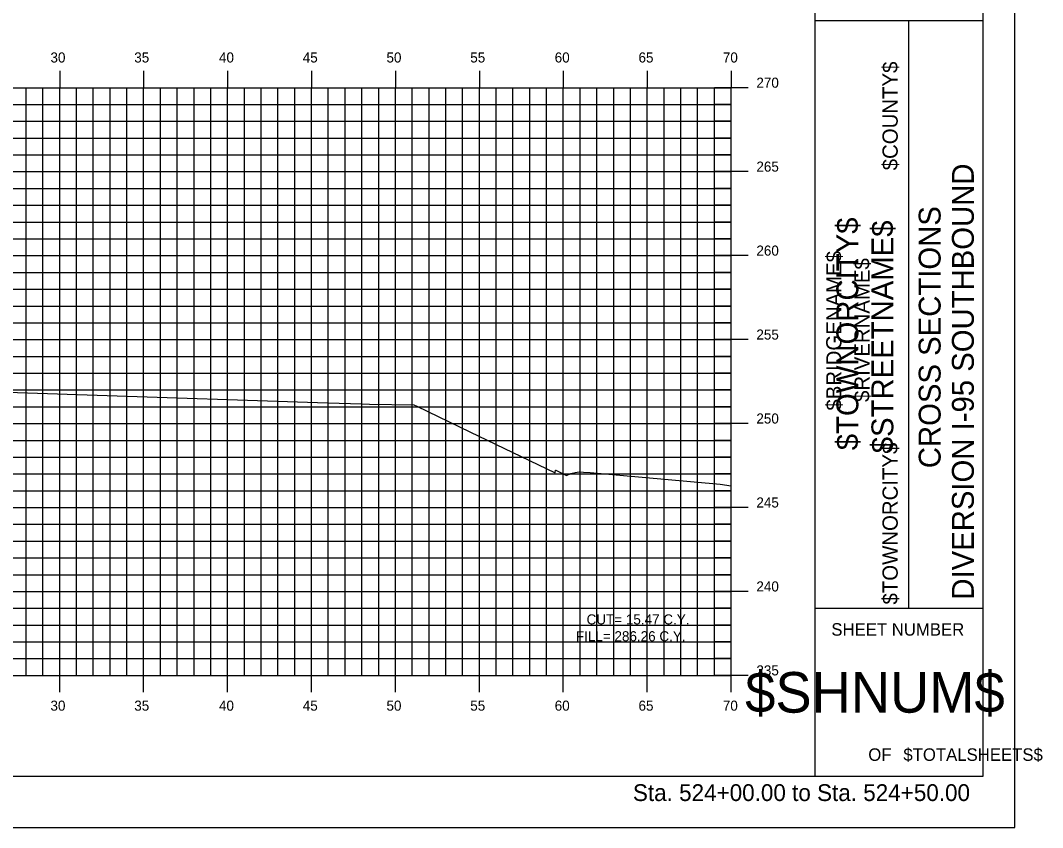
# Model space of a CAD drawing. Extents: x 1170543 to 1177585, y 609599 to 610623.
# Drawn here: x 1175384.7 to 1175445.6, y 609598.8 to 609646.9 of the extents above; entities that cross this region are included whole.
import ezdxf

# ---------------------------------------------------------------- set-up
doc = ezdxf.new("R2010")
doc.units = 0
for name, color, linetype in [('BORDER', 7, 'Continuous'), ('BRIDGE_TITLE', 7, 'Continuous'), ('D_Roadway_Centerline_Text', 7, 'Continuous'), ('H_V ANNOTATION', 7, 'Continuous'), ('HIGHWAY_TITLE', 7, 'Continuous'), ('MAJOR', 7, 'Continuous'), ('MINOR', 7, 'Continuous'), ('PLOT BOUNDARY', 7, 'Continuous'), ('S_Roadway_Centerline', 7, 'Continuous')]:
    doc.layers.add(name, color=color, linetype=linetype)

msp = doc.modelspace()

# ---------------------------------------------------------------- linework, layer by layer
at = {"layer": 'BORDER'}
for p, q in [((1175432.07, 609601.875), (1175432.07, 609706.875)), ((1175442.07, 609601.875), (1175442.07, 609706.875)), ((1175432.07, 609646.875), (1175442.07, 609646.875)), ((1175437.661, 609611.875), (1175437.661, 609646.875)), ((1175432.07, 609611.875), (1175442.07, 609611.875)), ((1175282.07, 609601.872), (1175442.07, 609601.872))]:
    msp.add_line(p, q, dxfattribs=at)
at = {"layer": 'MAJOR'}
for p, q in [((1175387.07, 609643.874), (1175387.07, 609642.872)), ((1175392.07, 609643.874), (1175392.07, 609642.872)), ((1175397.07, 609643.874), (1175397.07, 609642.872)), ((1175402.07, 609643.874), (1175402.07, 609642.872)), ((1175407.07, 609643.874), (1175407.07, 609642.872)), ((1175412.07, 609643.874), (1175412.07, 609642.872)), ((1175417.07, 609643.874), (1175417.07, 609642.872)), ((1175422.07, 609643.874), (1175422.07, 609642.872)), ((1175427.07, 609643.874), (1175427.07, 609642.872)), ((1175287.07, 609642.872), (1175427.07, 609642.872)), ((1175287.07, 609642.872), (1175427.07, 609642.872)), ((1175387.07, 609607.872), (1175387.07, 609642.872)), ((1175392.07, 609607.872), (1175392.07, 609642.872)), ((1175397.07, 609607.872), (1175397.07, 609642.872)), ((1175402.07, 609607.872), (1175402.07, 609642.872)), ((1175407.07, 609607.872), (1175407.07, 609642.872)), ((1175412.07, 609607.872), (1175412.07, 609642.872)), ((1175417.07, 609607.872), (1175417.07, 609642.872)), ((1175422.07, 609607.872), (1175422.07, 609642.872)), ((1175428.072, 609642.872), (1175426.068, 609642.872)), ((1175427.07, 609607.872), (1175427.07, 609642.872)), ((1175427.07, 609607.872), (1175427.07, 609642.872)), ((1175287.07, 609637.872), (1175427.07, 609637.872)), ((1175428.072, 609637.872), (1175426.068, 609637.872)), ((1175287.07, 609632.872), (1175427.07, 609632.872)), ((1175428.072, 609632.872), (1175426.068, 609632.872)), ((1175287.07, 609627.872), (1175427.07, 609627.872)), ((1175428.072, 609627.872), (1175426.068, 609627.872)), ((1175287.07, 609622.872), (1175427.07, 609622.872)), ((1175428.072, 609622.872), (1175426.068, 609622.872)), ((1175287.07, 609617.872), (1175427.07, 609617.872)), ((1175428.072, 609617.872), (1175426.068, 609617.872)), ((1175287.07, 609612.872), (1175427.07, 609612.872)), ((1175428.072, 609612.872), (1175426.068, 609612.872)), ((1175287.07, 609607.872), (1175427.07, 609607.872)), ((1175287.07, 609607.872), (1175427.07, 609607.872)), ((1175387.07, 609606.87), (1175387.07, 609607.872)), ((1175392.07, 609606.87), (1175392.07, 609607.872)), ((1175397.07, 609606.87), (1175397.07, 609607.872)), ((1175402.07, 609606.87), (1175402.07, 609607.872)), ((1175407.07, 609606.87), (1175407.07, 609607.872)), ((1175412.07, 609606.87), (1175412.07, 609607.872)), ((1175417.07, 609606.87), (1175417.07, 609607.872)), ((1175422.07, 609606.87), (1175422.07, 609607.872)), ((1175428.072, 609607.872), (1175426.068, 609607.872)), ((1175427.07, 609606.87), (1175427.07, 609607.872))]:
    msp.add_line(p, q, dxfattribs=at)
at = {"layer": 'MINOR'}
for p, q in [((1175385.07, 609607.872), (1175385.07, 609642.872)), ((1175386.07, 609607.872), (1175386.07, 609642.872)), ((1175388.07, 609607.872), (1175388.07, 609642.872)), ((1175389.07, 609607.872), (1175389.07, 609642.872)), ((1175390.07, 609607.872), (1175390.07, 609642.872)), ((1175391.07, 609607.872), (1175391.07, 609642.872)), ((1175393.07, 609607.872), (1175393.07, 609642.872)), ((1175394.07, 609607.872), (1175394.07, 609642.872)), ((1175395.07, 609607.872), (1175395.07, 609642.872)), ((1175396.07, 609607.872), (1175396.07, 609642.872)), ((1175398.07, 609607.872), (1175398.07, 609642.872)), ((1175399.07, 609607.872), (1175399.07, 609642.872)), ((1175400.07, 609607.872), (1175400.07, 609642.872)), ((1175401.07, 609607.872), (1175401.07, 609642.872)), ((1175403.07, 609607.872), (1175403.07, 609642.872)), ((1175404.07, 609607.872), (1175404.07, 609642.872)), ((1175405.07, 609607.872), (1175405.07, 609642.872)), ((1175406.07, 609607.872), (1175406.07, 609642.872)), ((1175408.07, 609607.872), (1175408.07, 609642.872)), ((1175409.07, 609607.872), (1175409.07, 609642.872)), ((1175410.07, 609607.872), (1175410.07, 609642.872)), ((1175411.07, 609607.872), (1175411.07, 609642.872)), ((1175413.07, 609607.872), (1175413.07, 609642.872)), ((1175414.07, 609607.872), (1175414.07, 609642.872)), ((1175415.07, 609607.872), (1175415.07, 609642.872)), ((1175416.07, 609607.872), (1175416.07, 609642.872)), ((1175418.07, 609607.872), (1175418.07, 609642.872)), ((1175419.07, 609607.872), (1175419.07, 609642.872)), ((1175420.07, 609607.872), (1175420.07, 609642.872)), ((1175421.07, 609607.872), (1175421.07, 609642.872)), ((1175423.07, 609607.872), (1175423.07, 609642.872)), ((1175424.07, 609607.872), (1175424.07, 609642.872)), ((1175425.07, 609607.872), (1175425.07, 609642.872)), ((1175426.07, 609607.872), (1175426.07, 609642.872)), ((1175287.07, 609641.872), (1175427.07, 609641.872)), ((1175427.07, 609641.872), (1175426.068, 609641.872)), ((1175287.07, 609640.872), (1175427.07, 609640.872)), ((1175427.07, 609640.872), (1175426.068, 609640.872)), ((1175287.07, 609639.872), (1175427.07, 609639.872)), ((1175427.07, 609639.872), (1175426.068, 609639.872)), ((1175287.07, 609638.872), (1175427.07, 609638.872)), ((1175427.07, 609638.872), (1175426.068, 609638.872)), ((1175287.07, 609636.872), (1175427.07, 609636.872)), ((1175427.07, 609636.872), (1175426.068, 609636.872)), ((1175287.07, 609635.872), (1175427.07, 609635.872)), ((1175427.07, 609635.872), (1175426.068, 609635.872)), ((1175287.07, 609634.872), (1175427.07, 609634.872)), ((1175427.07, 609634.872), (1175426.068, 609634.872)), ((1175287.07, 609633.872), (1175427.07, 609633.872)), ((1175427.07, 609633.872), (1175426.068, 609633.872)), ((1175287.07, 609631.872), (1175427.07, 609631.872)), ((1175427.07, 609631.872), (1175426.068, 609631.872)), ((1175287.07, 609630.872), (1175427.07, 609630.872)), ((1175427.07, 609630.872), (1175426.068, 609630.872)), ((1175287.07, 609629.872), (1175427.07, 609629.872)), ((1175427.07, 609629.872), (1175426.068, 609629.872)), ((1175287.07, 609628.872), (1175427.07, 609628.872)), ((1175427.07, 609628.872), (1175426.068, 609628.872)), ((1175287.07, 609626.872), (1175427.07, 609626.872)), ((1175427.07, 609626.872), (1175426.068, 609626.872)), ((1175287.07, 609625.872), (1175427.07, 609625.872)), ((1175427.07, 609625.872), (1175426.068, 609625.872)), ((1175287.07, 609624.872), (1175427.07, 609624.872)), ((1175427.07, 609624.872), (1175426.068, 609624.872)), ((1175287.07, 609623.872), (1175427.07, 609623.872)), ((1175427.07, 609623.872), (1175426.068, 609623.872)), ((1175287.07, 609621.872), (1175427.07, 609621.872)), ((1175427.07, 609621.872), (1175426.068, 609621.872)), ((1175287.07, 609620.872), (1175427.07, 609620.872)), ((1175427.07, 609620.872), (1175426.068, 609620.872)), ((1175287.07, 609619.872), (1175427.07, 609619.872)), ((1175427.07, 609619.872), (1175426.068, 609619.872)), ((1175287.07, 609618.872), (1175427.07, 609618.872)), ((1175427.07, 609618.872), (1175426.068, 609618.872)), ((1175287.07, 609616.872), (1175427.07, 609616.872)), ((1175427.07, 609616.872), (1175426.068, 609616.872)), ((1175287.07, 609615.872), (1175427.07, 609615.872)), ((1175427.07, 609615.872), (1175426.068, 609615.872)), ((1175287.07, 609614.872), (1175427.07, 609614.872)), ((1175427.07, 609614.872), (1175426.068, 609614.872)), ((1175287.07, 609613.872), (1175427.07, 609613.872)), ((1175427.07, 609613.872), (1175426.068, 609613.872)), ((1175287.07, 609611.872), (1175427.07, 609611.872)), ((1175427.07, 609611.872), (1175426.068, 609611.872)), ((1175287.07, 609610.872), (1175427.07, 609610.872)), ((1175427.07, 609610.872), (1175426.068, 609610.872)), ((1175287.07, 609609.872), (1175427.07, 609609.872)), ((1175427.07, 609609.872), (1175426.068, 609609.872)), ((1175287.07, 609608.872), (1175427.07, 609608.872)), ((1175427.07, 609608.872), (1175426.068, 609608.872))]:
    msp.add_line(p, q, dxfattribs=at)
at = {"layer": 'PLOT BOUNDARY'}
msp.add_lwpolyline([(1175273.976, 609598.813), (1175443.976, 609598.813), (1175443.976, 609708.813), (1175273.976, 609708.813)], close=True, dxfattribs=at)
at = {"layer": 'S_Roadway_Centerline'}
msp.add_lwpolyline([(1175372.704, 609625.117), (1175388.699, 609624.584), (1175403.015, 609624.106), (1175405.091, 609624.038), (1175405.515, 609624.033), (1175408.165, 609623.996), (1175408.353, 609623.905), (1175411.51, 609622.383), (1175416.583, 609619.936), (1175416.607, 609620.09), (1175416.633, 609620.09), (1175417.261, 609619.777), (1175417.518, 609619.895), (1175417.772, 609619.966), (1175418.023, 609619.99), (1175418.271, 609619.97), (1175418.668, 609619.962), (1175426.42, 609619.268), (1175427.07, 609619.164)], dxfattribs=at)

# ---------------------------------------------------------------- texts
at = {"layer": 'BORDER'}
for s, height, rotation, p in [('DIVERSION I-95 SOUTHBOUND', 1.30428, 90, (1175441.524, 609612.385)), ('CROSS SECTIONS', 1.30428, 90, (1175439.545, 609620.214)), ('SHEET NUMBER', 0.74527, 360, (1175433.035, 609610.239)), ('$SHNUM$', 2.4194, 360, (1175427.903, 609605.655)), ('OF', 0.7453, 360, (1175435.237, 609602.785)), ('$TOTALSHEETS$', 0.74527, 360, (1175437.326, 609602.785))]:
    msp.add_text(s, height=height, rotation=rotation, dxfattribs=at).set_placement(p)
at = {"layer": 'BRIDGE_TITLE'}
for s, height, p in [('$COUNTY$', 0.9072, (1175436.99, 609637.954)), ('$BRIDGENAME$', 0.90716, (1175433.636, 609623.643)), ('$RIVERNAME$', 0.90716, (1175435.313, 609624.158)), ('$TOWNORCITY$', 0.90716, (1175436.99, 609612.096))]:
    msp.add_text(s, height=height, rotation=90, dxfattribs=at).set_placement(p)
at = {"layer": 'D_Roadway_Centerline_Text'}
for s, p in [('CUT= 15.47 C.Y.', (1175418.455, 609610.908)), ('FILL= 286.26 C.Y.', (1175417.819, 609609.906))]:
    msp.add_text(s, height=0.6, dxfattribs=at).set_placement(p)
at = {"layer": 'H_V ANNOTATION'}
for s, height, p in [('30', 0.6, (1175386.518, 609644.372)), ('35', 0.6, (1175391.51, 609644.372)), ('40', 0.6, (1175396.556, 609644.372)), ('45', 0.6, (1175401.548, 609644.372)), ('50', 0.6, (1175406.534, 609644.372)), ('55', 0.6, (1175411.526, 609644.372)), ('60', 0.6, (1175416.556, 609644.372)), ('65', 0.6, (1175421.548, 609644.372)), ('70', 0.6, (1175426.572, 609644.372)), ('270', 0.6, (1175428.57, 609642.872)), ('265', 0.6, (1175428.57, 609637.872)), ('260', 0.6, (1175428.57, 609632.872)), ('255', 0.6, (1175428.57, 609627.872)), ('250', 0.6, (1175428.57, 609622.872)), ('245', 0.6, (1175428.57, 609617.872)), ('240', 0.6, (1175428.57, 609612.872)), ('235', 0.6, (1175428.57, 609607.872)), ('30', 0.6, (1175386.518, 609605.772)), ('35', 0.6, (1175391.51, 609605.772)), ('40', 0.6, (1175396.556, 609605.772)), ('45', 0.6, (1175401.548, 609605.772)), ('50', 0.6, (1175406.534, 609605.772)), ('55', 0.6, (1175411.526, 609605.772)), ('60', 0.6, (1175416.556, 609605.772)), ('65', 0.6, (1175421.548, 609605.772)), ('70', 0.6, (1175426.572, 609605.772)), ('Sta. 524+00.00 to Sta. 524+50.00', 1.0002, (1175421.216, 609600.392))]:
    msp.add_text(s, height=height, dxfattribs=at).set_placement(p)
at = {"layer": 'HIGHWAY_TITLE'}
for s, p in [('$TOWNORCITY$', (1175434.642, 609621.284)), ('$STREETNAME$', (1175436.729, 609621.104))]:
    msp.add_text(s, height=1.30428, rotation=90, dxfattribs=at).set_placement(p)

doc.saveas('drawing.dxf')
